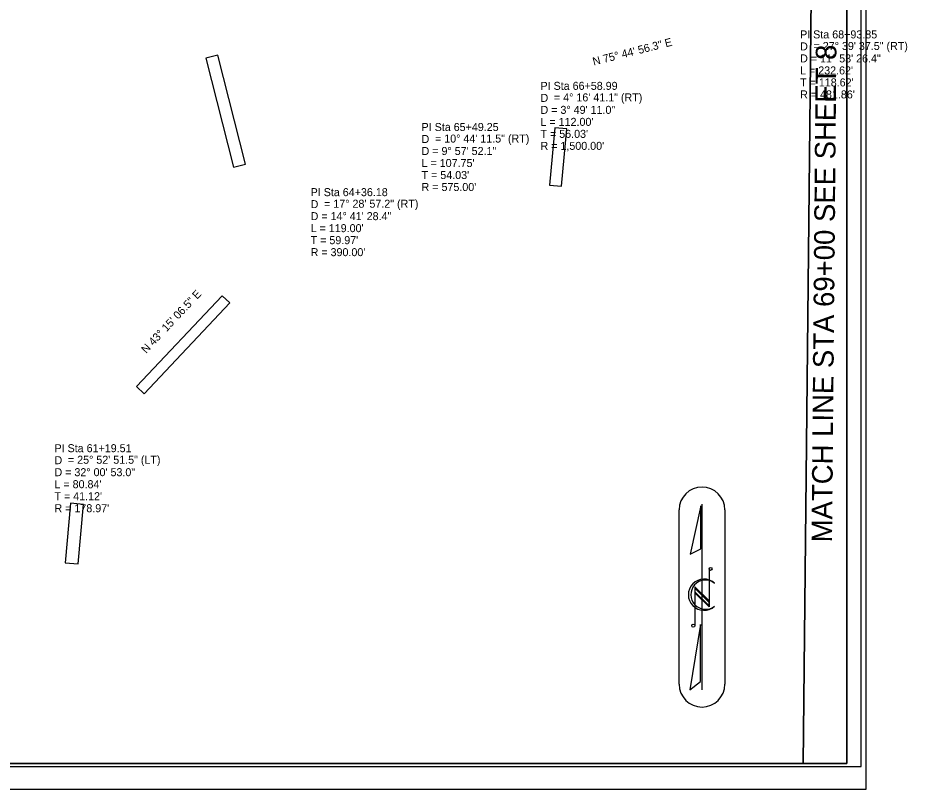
# Model space of a CAD drawing. Extents: x 928111 to 937215, y 684185 to 686530.
# Drawn here: x 932495 to 933273, y 684185 to 684860 of the extents above; entities that cross this region are included whole.
import ezdxf

# ---------------------------------------------------------------- set-up
doc = ezdxf.new("R2010")
doc.units = 0
for name, color, linetype in [('Exist Horizontal Alignment Curve and Spiral Data', 7, 'Continuous'), ('Exist Horizontal Alignment Direction Label', 7, 'Continuous'), ('Exist Horizontal Alignment Station Label', 7, 'Continuous'), ('Matchline', 7, 'Continuous'), ('Matchline Text', 7, 'Continuous'), ('Prop DSN Text', 7, 'Continuous'), ('Sheet Cutting Line CELL', 7, 'Continuous'), ('Sheet Layout Plan Border', 7, 'Continuous'), ('Sheet Plan CELL', 7, 'Continuous'), ('Sheet Plan Layout CELL', 7, 'Continuous'), ('Sheet Plot Border Outside CELL', 7, 'Continuous')]:
    doc.layers.add(name, color=color, linetype=linetype)

msp = doc.modelspace()

# ---------------------------------------------------------------- linework, layer by layer
at = {"layer": 'Exist Horizontal Alignment Station Label'}
for p, q in [((933073.23, 684277.02), (933073.23, 684429.52)), ((933113.23, 684429.52), (933113.23, 684277.02))]:
    msp.add_line(p, q, dxfattribs=at)
for centre, start, end in [((933093.23, 684429.52), 90, 180), ((933093.23, 684429.52), 0, 90), ((933093.23, 684277.02), 180, 270), ((933093.23, 684277.02), 270, 0)]:
    msp.add_arc(centre, 20, start, end, dxfattribs=at)
at = {"layer": 'Matchline'}
msp.add_line((933190.31, 685046.18), (933181.74, 684207.66), dxfattribs=at)
at = {"layer": 'Prop DSN Text'}
for points in [[(932694.01, 684731.97), (932669.85, 684827.44), (932659.37, 684824.79), (932683.53, 684729.32)], [(932964.66, 684763.78), (932959.95, 684713.62), (932970.25, 684712.65), (932974.96, 684762.81)], [(932605.36, 684531.12), (932680.19, 684610.67), (932673.57, 684616.89), (932598.74, 684537.34)], [(932540.86, 684435.35), (932536.43, 684383.21), (932547.83, 684382.24), (932552.26, 684434.38)]]:
    msp.add_lwpolyline(points, close=True, dxfattribs=at)
at = {"layer": 'Sheet Cutting Line CELL'}
msp.add_line((931553.29, 684185.15), (933236.79, 684185.15), dxfattribs=at)
at = {"layer": 'Sheet Layout Plan Border'}
msp.add_line((933181.74, 684207.66), (933190.31, 685046.18), dxfattribs=at)
at = {"layer": 'Sheet Plan CELL'}
for p, q in [((933093.23, 684272.02), (933093.23, 684434.52)), ((933099.36, 684377.97), (933099.36, 684344.62)), ((933103.96, 684365.54), (933104.13, 684365.42)), ((933099.36, 684349.82), (933086.93, 684362.24)), ((933086.93, 684362.24), (933086.93, 684328.34)), ((933099.36, 684348.59), (933086.93, 684361.02)), ((933086.93, 684361.02), (933086.93, 684357.97)), ((933099.36, 684345.54), (933086.93, 684357.97)), ((933086.93, 684357.97), (933099.36, 684345.54)), ((933099.36, 684344.62), (933086.93, 684357.04)), ((933099.36, 684345.54), (933099.36, 684348.59))]:
    msp.add_line(p, q, dxfattribs=at)
for points in [[(931566.29, 684205.15), (933232.28, 684205.16), (933232.29, 685260.15), (931566.29, 685260.15)], [(931719.78, 684207.66), (931719.75, 685257.64), (933019.74, 685257.68), (933019.75, 685107.61), (933219.79, 685107.6), (933219.79, 684207.66)], [(933219.81, 685257.66), (931719.78, 685257.66), (931719.78, 684207.66), (933219.79, 684207.66)], [(933092.11, 684433.09), (933082.83, 684390.89), (933092.11, 684395.59)], [(933091.91, 684329.27), (933082.71, 684272.02), (933091.91, 684279.27)]]:
    msp.add_lwpolyline(points, close=True, dxfattribs=at)
for centre in [(933100.68, 684377.94), (933085.61, 684328.29)]:
    msp.add_circle(centre, 1.32, dxfattribs=at)
for centre, radius, start, end in [((933094.96, 684355.3), 13.65, 47.84002, 312.39406), ((933096.28, 684355.31), 12.8, 53.09504, 308.62871)]:
    msp.add_arc(centre, radius, start, end, dxfattribs=at)
at = {"layer": 'Sheet Plan Layout CELL'}
msp.add_lwpolyline([(931719.75, 685257.64), (931719.78, 684207.66), (933219.78, 684207.66), (933219.78, 685046.18), (932980.53, 685046.18), (932980.53, 685257.66)], close=True, dxfattribs=at)
at = {"layer": 'Sheet Plot Border Outside CELL'}
msp.add_lwpolyline([(931553.29, 684185.15), (933236.79, 684185.15), (933236.79, 685280.15), (931553.29, 685280.15)], close=True, dxfattribs=at)

# ---------------------------------------------------------------- texts
at = {"layer": 'Exist Horizontal Alignment Curve and Spiral Data'}
for s, p in [('PI Sta 68+93.85', (933179, 684842)), ('D', (933179, 684831.5)), ('= 27%%d 39\' 37.5" (RT)', (933190.77, 684831.89)), ('D = 11%%d 53\' 26.4"', (933179, 684821)), ("L = 232.62'", (933179, 684810.5)), ("T = 118.62'", (933179, 684800)), ('PI Sta 66+58.99', (932952, 684797)), ('D', (932952, 684786.5)), ('= 4%%d 16\' 41.1" (RT)', (932963.77, 684786.89)), ("R = 481.86'", (933179, 684789.5)), ('D = 3%%d 49\' 11.0"', (932952, 684776)), ('PI Sta 65+49.25', (932848, 684761)), ("L = 112.00'", (932952, 684765.5)), ("T = 56.03'", (932952, 684755)), ('D', (932848, 684750.5)), ('= 10%%d 44\' 11.5" (RT)', (932859.77, 684750.89)), ('D = 9%%d 57\' 52.1"', (932848, 684740)), ("R = 1,500.00'", (932952, 684744.5)), ("L = 107.75'", (932848, 684729.5)), ("T = 54.03'", (932848, 684719)), ("R = 575.00'", (932848, 684708.5)), ('PI Sta 64+36.18', (932751, 684704)), ('D', (932751, 684693.5)), ('= 17%%d 28\' 57.2" (RT)', (932762.77, 684693.89)), ('D = 14%%d 41\' 28.4"', (932751, 684683)), ("L = 119.00'", (932751, 684672.5)), ("T = 59.97'", (932751, 684662)), ("R = 390.00'", (932751, 684651.5)), ('PI Sta 61+19.51', (932527, 684480)), ('D', (932527, 684469.5)), ('= 25%%d 52\' 51.5" (LT)', (932538.77, 684469.89)), ('D = 32%%d 00\' 53.0"', (932527, 684459)), ("L = 80.84'", (932527, 684448.5)), ("T = 41.12'", (932527, 684438)), ("R = 178.97'", (932527, 684427.5))]:
    msp.add_text(s, height=7, dxfattribs=at).set_placement(p)
at = {"layer": 'Exist Horizontal Alignment Direction Label'}
for s, rotation, p in [('N 75%%d 44\' 56.3" E', 14.25102, (932998.53, 684818.24)), ('N 43%%d 15\' 06.5" E', 46.74818, (932607.16, 684565.97))]:
    msp.add_text(s, height=7, rotation=rotation, dxfattribs=at).set_placement(p)
at = {"layer": 'Matchline Text'}
msp.add_text('MATCH LINE STA 69+00 SEE SHEET 8 ', height=18, rotation=89.49614, dxfattribs=at).set_placement((933206.95, 684401.05))

doc.saveas('drawing.dxf')
